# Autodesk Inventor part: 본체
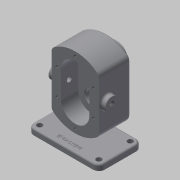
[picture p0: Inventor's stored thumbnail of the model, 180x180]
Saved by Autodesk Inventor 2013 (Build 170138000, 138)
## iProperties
Created: 2019-03
Part Number: 본체
Material: Generic
Document SubType Name: Modeling
Designer: Administrator
Density: 1 g/cm^3
Author: Administrator
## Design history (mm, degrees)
sketch "스케치5"
  geometry: L1 (-40, 44.721)-(40, 44.721); L2 (40, 44.721)-(40, -44.721); L3 (40, -44.721)-(-40, -44.721); L4 (-40, -44.721)-(-40, 44.721); A1 r 60 centre (0, 0) between (40, 44.721) and (-40, 44.721); A2 r 60 centre (0, 0) between (-40, -44.721) and (40, -44.721); 3 further points
  constraints: 8 end point, 4 point on circle, 2 centre point, 2 coincident, 2 midpoint, 2 parallel, 1 horizontal, 1 perpendicular, 1 vertical alignment
  dimensions: "d17" = 80 distance of L2.end L3.end; "d20" = 60 radius of A1; "d21" = 60 radius of A2
extrude "돌출2" new body sketch "스케치5" distance "d22" = 53; taper "d23" = 0 deg
sketch "스케치7"
  geometry: L1 (-24, 22)-(-24, -22); L2 (24, 22)-(24, -22); A1 r 60 centre (0, 0) between (40, 44.721) and (-40, 44.721) reference; A2 r 24 centre (0, -22) between (-24, -22) and (24, -22); A3 r 24 centre (0, 22) between (24, 22) and (-24, 22)
  constraints: 4 end point, 4 point on circle, 4 tangent, 2 centre point, 2 vertical alignment
  dimensions: "d25" = 24 radius of A2; "d26" = 22 distance of A1.centre A3.centre; "d27" = 44 distance of A2.centre A3.centre; "d28" = 24 radius of A3
extrude "돌출3" cut sketch "스케치7" distance "d29" = 29; taper "d30" = 0 deg
sketch "스케치8"
  geometry: C1 r 12.5 at (0, 22); C2 r 12.5 at (0, -22); A1 r 24 centre (0, -22) between (-24, -22) and (24, -22) reference; A2 r 24 centre (0, 22) between (24, 22) and (-24, 22) reference; 1 further point
  constraints: 2 centre point, 2 coincident
  dimensions: "d31" = 25 diameter of C1; "d32" = 25 diameter of C2
extrude "돌출4" cut sketch "스케치8" distance "d33" = 15; taper "d34" = 0 deg
sketch "스케치9"
  geometry: C1 r 12.5 at (0, 22) reference; C2 r 12.5 at (0, -22) reference; C3 r 19 at (0, 22)
  constraints: 1 centre point, 1 coincident
  dimensions: "d35" = 38 diameter of C3
extrude "돌출5" join sketch "스케치9" distance "d36" = 17; taper "d37" = 0 deg
sketch "스케치10"
  geometry: C1 r 19 at (0, 0) reference; C2 r 14 at (0, 0); 1 further point
  constraints: 1 centre point, 1 coincident
  dimensions: "d38" = 28 diameter of C2
extrude "돌출6" cut sketch "스케치10" distance "d39" = 7.3; taper "d40" = 0 deg
sketch "스케치11"
  geometry: C1 r 12.5 at (0, 0) reference; C2 r 8.5 at (0, 0); 1 further point
  constraints: 1 centre point, 1 coincident
  dimensions: "d41" = 17 diameter of C2
hole "구멍2" sketch "스케치11" at (0, 0) diameter "d42" = 17; stored, may be unused: countersink angle "d46" = 90 deg, drill point angle "d48" = 118 deg; dims "d43" = 6, "d44" = 4, "d45" = 2, "d47" = 8
node "작업 평면2"
sketch "스케치12"
  geometry: L1 (60, 73)-(-60, 73); L2 (-60, 73)-(-60, 0); L3 (-60, 0)-(60, 0); L4 (60, 0)-(60, 73); L5 (40, 0)-(-40, 0) reference; 3 further points
  constraints: 8 end point, 2 midpoint, 2 parallel, 1 coincident, 1 horizontal, 1 perpendicular
  dimensions: "d50" = 73 distance of L3.end L1.start; "d52" = 120 distance of L1.start L1.end
extrude "돌출7" join sketch "스케치12" distance "d53" = 10; taper "d54" = 0 deg
fillet "모깎기3" dims "d55" = 10
sketch "스케치13"
  geometry: A1 r 10 centre (-50, -63) between (-60, -63) and (-50, -73) reference; A2 r 10 centre (50, -63) between (50, -73) and (60, -63) reference; A3 r 10 centre (50, -10) between (60, -10) and (50, 0) reference; A4 r 10 centre (-50, -10) between (-50, 0) and (-60, -10) reference; 1 further point
hole "구멍3" sketch "스케치13" at (50, -10), (50, -63), (-50, -10), (-50, -63) diameter "d56" = 9; stored, may be unused: countersink angle "d60" = 90 deg, drill point angle "d62" = 118 deg; dims "d57" = 6, "d58" = 4, "d59" = 2, "d61" = 8
sketch "스케치15"
  geometry: L1 (-6, 0)-(6, 0); L2 (6, 0)-(6, -43); L3 (6, -43)-(-6, -43); L4 (-6, -43)-(-6, 0); 2 further points
  constraints: 8 end point, 2 parallel, 1 coincident, 1 horizontal, 1 midpoint, 1 perpendicular
  dimensions: "d64" = 12 distance of L2.end L3.end; "d65" = 43 distance of L1.end L2.end
extrude "돌출8" join sketch "스케치15" stored distance "d66" = 10; taper "d67" = 0 deg
fillet "모깎기5" dims "d68" = 3
sketch "스케치16"
  geometry: L1 (0, 89.443)-(-53, 89.443) reference; L2 (-63, -33.279)-(-10, -33.279) reference; L3 (-53, 0)-(-53, 89.443) reference; C1 r 11 at (-39, 44.721); 2 further points
  constraints: 1 centre point, 1 midpoint
  dimensions: "d69" = 22 diameter of C1; "d70" = 78 distance from line of L2 C1.centre; "d73" = 14 distance from line of L3 C1.centre
extrude "돌출9" join sketch "스케치16" distance "d71" = 8; taper "d72" = 0 deg
sketch "스케치19"
  geometry: C1 r 11 at (0, 0) reference; 1 further point
hole "구멍4" sketch "스케치19" at (0, 0) diameter "d74" = 8.376; stored, may be unused: countersink angle "d78" = 90 deg, drill point angle "d80" = 118 deg; dims "d75" = 10, "d76" = 4, "d77" = 2, "d79" = 8
sketch "스케치20"
  geometry: L1 (-31, -22)-(-31, 22); L2 (31, 22)-(31, -22); A1 r 24 centre (0, -22) between (-24, -22) and (24, -22) reference; A2 r 24 centre (0, 22) between (24, 22) and (-24, 22) reference; A3 r 31 centre (0, 22) between (31, 22) and (-31, 22); A4 r 31 centre (0, -22) between (-31, -22) and (31, -22); 8 further points
  constraints: 8 coincident, 6 point on circle, 4 end point, 4 tangent, 2 centre point
  dimensions: "d84" = 31 radius of A3; "d86" = 31 radius of A4
hole "구멍5" sketch "스케치20" diameter "d87" = 4.134; stored, may be unused: countersink angle "d91" = 90 deg, drill point angle "d93" = 118 deg; dims "d88" = 10, "d89" = 4, "d90" = 2, "d92" = 12
hole "구멍6" sketch "스케치20" diameter "d94" = 4.134; stored, may be unused: countersink angle "d98" = 90 deg, drill point angle "d100" = 118 deg; dims "d95" = 10, "d96" = 4, "d97" = 2, "d99" = 12
chamfer "모따기1" distance "d101" = 0.7; stored, may be unused: second distance "d102" = 2, angle "d103" = 30 deg
sketch "스케치21"
  geometry: L1 (-27.63, -55.961)-(27.63, -55.961); L2 (27.63, -55.961)-(27.63, -68.726); L3 (27.63, -68.726)-(-27.63, -68.726); L4 (-27.63, -68.726)-(-27.63, -55.961); L5 (-50, -73)-(50, -73) reference; 3 further points
  constraints: 2 midpoint, 1 vertical alignment, 2 other
  dimensions: "d104" = 12.7654 distance of L1.end L2.end
feature "엠보싱1" sketch "스케치21" dims "d17" = 80, "d20" = 60, "d21" = 60, "d107" = 0.5, "d108" = 0
fillet "모깎기6" dims "d109" = 10
fillet "모깎기7" dims "d110" = 3
chamfer "모따기2" distance "d111" = 1; stored, may be unused: second distance "d112" = 2, angle "d113" = 30 deg
fillet "모깎기8" dims "d114" = 3
node "솔리드2"
mirror "대칭1"
mirror "대칭2"
other parameters: "d24" = 24, "d49" = -78, "d81" = 31, "d83" = 31
